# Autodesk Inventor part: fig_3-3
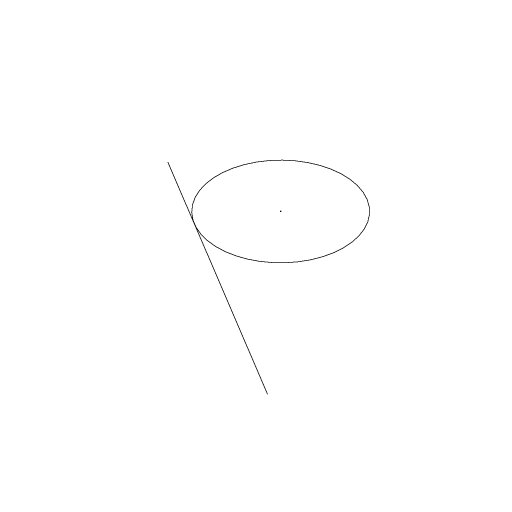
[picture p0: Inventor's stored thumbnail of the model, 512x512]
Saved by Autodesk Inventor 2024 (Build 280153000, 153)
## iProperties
Created: 2009-11
Part Number: fig_3-3
Document SubType Name: Modeling
Designer: Sham
Density: 1 g/cm^3
Material: Generic
Appearance: Default
Author: Sham
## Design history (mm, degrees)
sketch "Sketch1"
  geometry: L1 (-21, -10.296)-(20, -35); C1 r 10.296 at (-4.831, -8.018)
  constraints: 2 end point, 1 centre point, 1 tangent, 1 other
